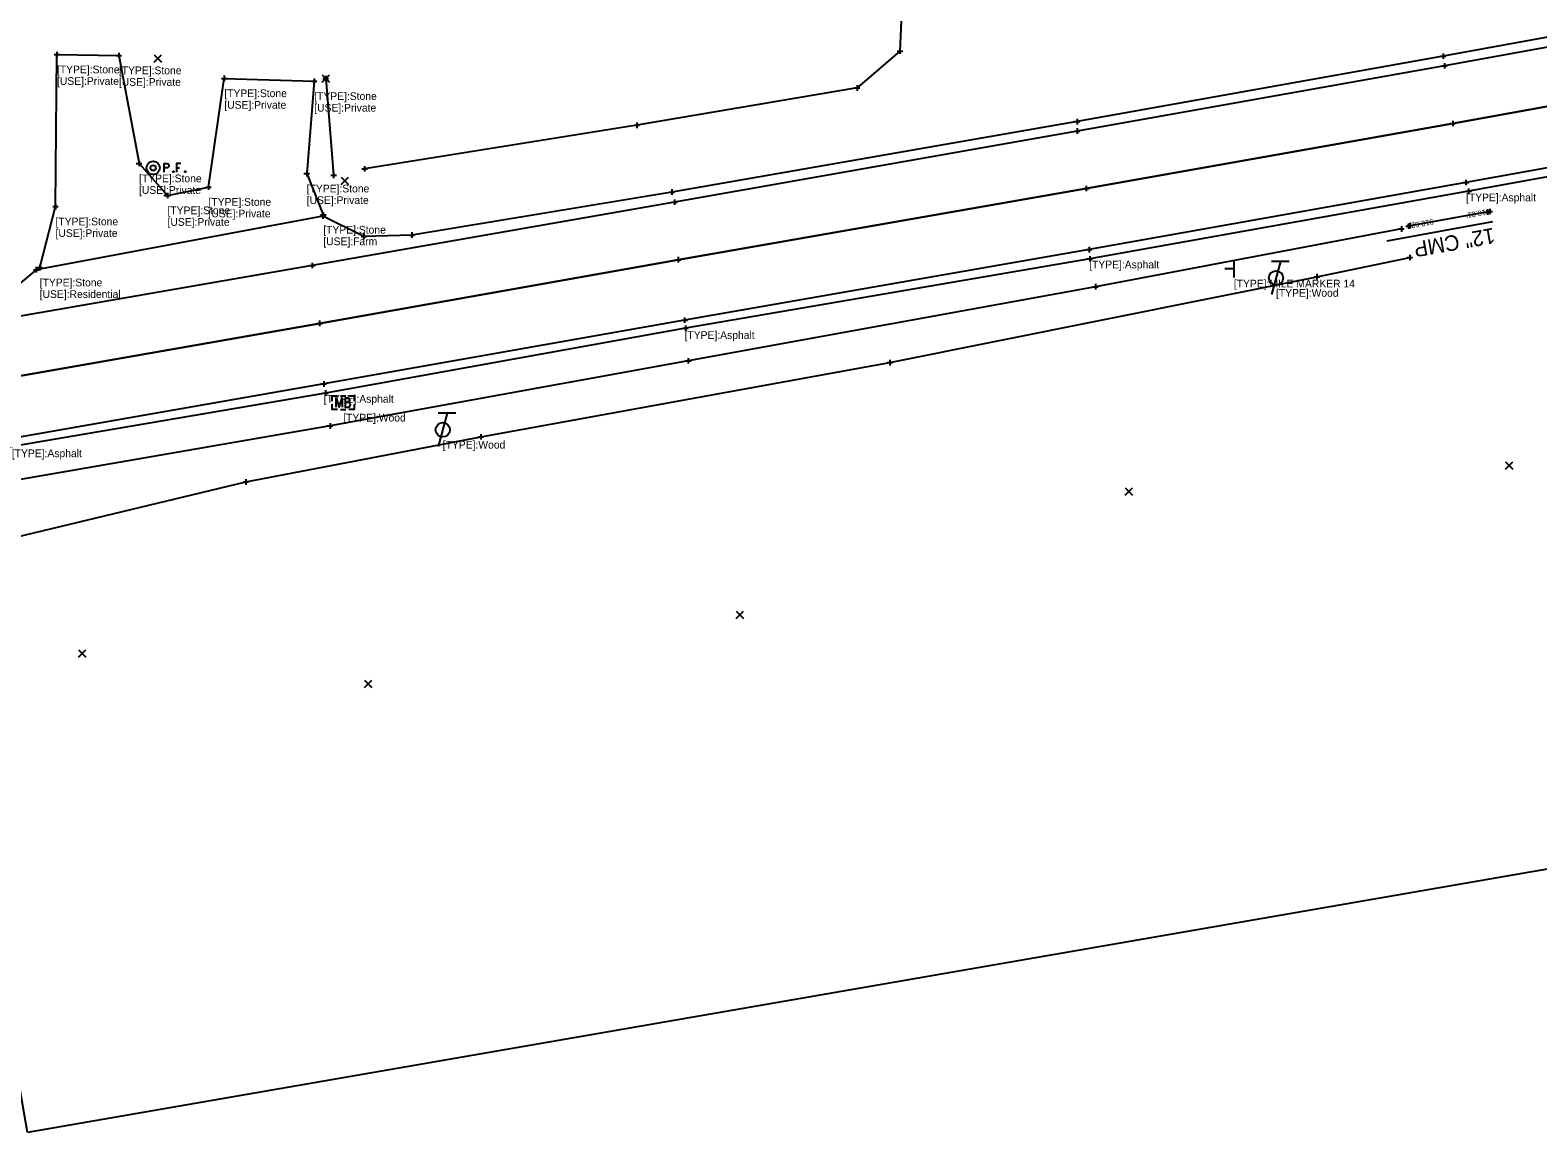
# Model space of a CAD drawing. Extents: x 1386013 to 1389776, y 604170 to 607009.
# Drawn here: x 1388733.1 to 1389006.3, y 604902.7 to 605103.7 of the extents above; entities that cross this region are included whole.
import ezdxf

# ---------------------------------------------------------------- set-up
doc = ezdxf.new("R2010")
doc.units = 0
for name, color, linetype in [('DR_X_Elev_Flow', 7, 'Continuous'), ('DR_X_Storm_Sewer', 7, 'Continuous'), ('DR_X_Text', 7, 'Continuous'), ('DV_X_Text', 7, 'Continuous'), ('PM_X_CL_Double_Solid', 7, 'Continuous'), ('PV_X_COP', 7, 'Continuous'), ('PV_X_Driveway', 7, 'Continuous'), ('PV_X_EOP', 7, 'Continuous'), ('PV_X_Shoulder', 7, 'Continuous'), ('RD_X_Cells', 7, 'Continuous'), ('RD_X_Fence', 7, 'Continuous'), ('SC_Scratch1', 7, 'Continuous'), ('SH_Cut_Line', 7, 'Continuous'), ('SN_X_Public', 7, 'Continuous'), ('SV_X_Random_Point', 7, 'Continuous'), ('SV_X_Text', 7, 'Continuous'), ('SV_X_Toe_of_Slope', 7, 'Continuous'), ('SV_X_Top_of_Bank', 7, 'Continuous'), ('UT_X_Telecom_Cells', 7, 'Continuous')]:
    doc.layers.add(name, color=color, linetype=linetype)

msp = doc.modelspace()

# ---------------------------------------------------------------- linework, layer by layer
at = {"layer": 'DR_X_Elev_Flow'}
for p, q in [((1388997.1, 605070.86), (1388998.1, 605070.86)), ((1388997.6, 605071.36), (1388997.6, 605070.36)), ((1388997.6, 605070.86), (1388997.6, 605070.86)), ((1388982.36, 605068.2), (1388983.36, 605068.2)), ((1388982.86, 605068.7), (1388982.86, 605067.7)), ((1388982.86, 605068.2), (1388982.86, 605068.2))]:
    msp.add_line(p, q, dxfattribs=at)
at = {"layer": 'DR_X_Storm_Sewer'}
msp.add_line((1388997.6, 605070.86), (1388982.86, 605068.2), dxfattribs=at)
at = {"layer": 'DR_X_Text'}
msp.add_line((1388979.02, 605065.57), (1388998.18, 605069.03), dxfattribs=at)
at = {"layer": 'DV_X_Text'}
for p, q in [((1388737.98, 605099.78), (1388737.98, 605098.78)), ((1388749.2, 605099.62), (1388749.2, 605098.62)), ((1388890.22, 605099.89), (1388891.22, 605099.89)), ((1388890.72, 605100.39), (1388890.72, 605099.39)), ((1388890.72, 605099.89), (1388890.72, 605099.89)), ((1388989.16, 605099.49), (1388989.16, 605098.49)), ((1388737.48, 605099.28), (1388738.48, 605099.28)), ((1388737.98, 605099.28), (1388737.98, 605099.28)), ((1388748.7, 605099.12), (1388749.7, 605099.12)), ((1388749.2, 605099.12), (1388749.2, 605099.12)), ((1388988.66, 605098.99), (1388989.66, 605098.99)), ((1388988.89, 605097.25), (1388989.89, 605097.25)), ((1388989.16, 605098.99), (1388989.16, 605098.99)), ((1388989.39, 605097.75), (1388989.39, 605096.75)), ((1388989.39, 605097.25), (1388989.39, 605097.25)), ((1388767.8, 605094.97), (1388768.8, 605094.97)), ((1388768.3, 605095.47), (1388768.3, 605094.47)), ((1388768.3, 605094.97), (1388768.3, 605094.97)), ((1388784.09, 605094.45), (1388785.09, 605094.45)), ((1388784.59, 605094.95), (1388784.59, 605093.95)), ((1388784.59, 605094.45), (1388784.59, 605094.45)), ((1388786.18, 605094.92), (1388787.18, 605094.92)), ((1388786.68, 605095.42), (1388786.68, 605094.42)), ((1388786.68, 605094.92), (1388786.68, 605094.92)), ((1388882.48, 605093.24), (1388883.48, 605093.24)), ((1388882.98, 605093.74), (1388882.98, 605092.74)), ((1388882.98, 605093.24), (1388882.98, 605093.24)), ((1388842.55, 605086.47), (1388843.55, 605086.47)), ((1388843.05, 605086.97), (1388843.05, 605085.97)), ((1388843.05, 605086.47), (1388843.05, 605086.47)), ((1388922.31, 605087.13), (1388923.31, 605087.13)), ((1388922.81, 605087.63), (1388922.81, 605086.63)), ((1388922.81, 605087.13), (1388922.81, 605087.13)), ((1388922.83, 605085.93), (1388922.83, 605084.93)), ((1388990.4, 605086.8), (1388991.4, 605086.8)), ((1388990.9, 605087.3), (1388990.9, 605086.3)), ((1388990.9, 605086.8), (1388990.9, 605086.8)), ((1388922.33, 605085.43), (1388923.33, 605085.43)), ((1388922.83, 605085.43), (1388922.83, 605085.43)), ((1388752.35, 605079.55), (1388753.35, 605079.55)), ((1388752.85, 605080.05), (1388752.85, 605079.05)), ((1388752.85, 605079.55), (1388752.85, 605079.55)), ((1388782.73, 605077.71), (1388783.73, 605077.71)), ((1388783.23, 605078.21), (1388783.23, 605077.21)), ((1388783.23, 605077.71), (1388783.23, 605077.71)), ((1388788.1, 605077.91), (1388788.1, 605076.91)), ((1388793.22, 605078.57), (1388794.22, 605078.57)), ((1388793.72, 605079.07), (1388793.72, 605078.07)), ((1388793.72, 605078.57), (1388793.72, 605078.57)), ((1388764.94, 605075.29), (1388765.94, 605075.29)), ((1388765.44, 605075.79), (1388765.44, 605074.79)), ((1388765.44, 605075.29), (1388765.44, 605075.29)), ((1388787.6, 605077.41), (1388788.6, 605077.41)), ((1388788.1, 605077.41), (1388788.1, 605077.41)), ((1388849.4, 605074.88), (1388849.4, 605073.88)), ((1388923.99, 605075.02), (1388924.99, 605075.02)), ((1388924.49, 605075.52), (1388924.49, 605074.52)), ((1388924.49, 605075.02), (1388924.49, 605075.02)), ((1388992.79, 605076.1), (1388993.79, 605076.1)), ((1388993.29, 605076.6), (1388993.29, 605075.6)), ((1388993.29, 605076.1), (1388993.29, 605076.1)), ((1388993.76, 605075.01), (1388993.76, 605074.01)), ((1388737.72, 605072.24), (1388737.72, 605071.24)), ((1388757.51, 605073.76), (1388758.51, 605073.76)), ((1388758.01, 605074.26), (1388758.01, 605073.26)), ((1388758.01, 605073.76), (1388758.01, 605073.76)), ((1388848.9, 605074.38), (1388849.9, 605074.38)), ((1388849.36, 605072.55), (1388850.36, 605072.55)), ((1388849.4, 605074.38), (1388849.4, 605074.38)), ((1388849.86, 605073.05), (1388849.86, 605072.05)), ((1388849.86, 605072.55), (1388849.86, 605072.55)), ((1388993.26, 605074.51), (1388994.26, 605074.51)), ((1388993.76, 605074.51), (1388993.76, 605074.51)), ((1388737.22, 605071.74), (1388738.22, 605071.74)), ((1388737.72, 605071.74), (1388737.72, 605071.74)), ((1388785.66, 605070.01), (1388786.66, 605070.01)), ((1388785.73, 605070.25), (1388786.73, 605070.25)), ((1388786.16, 605070.51), (1388786.16, 605069.51)), ((1388786.16, 605070.01), (1388786.16, 605070.01)), ((1388786.23, 605070.75), (1388786.23, 605069.75)), ((1388786.23, 605070.25), (1388786.23, 605070.25)), ((1388996.7, 605070.73), (1388997.7, 605070.73)), ((1388997.2, 605071.23), (1388997.2, 605070.23)), ((1388997.2, 605070.73), (1388997.2, 605070.73)), ((1388793.59, 605066.84), (1388793.59, 605065.84)), ((1388801.79, 605066.59), (1388802.79, 605066.59)), ((1388802.29, 605067.09), (1388802.29, 605066.09)), ((1388802.29, 605066.59), (1388802.29, 605066.59)), ((1388981.1, 605067.69), (1388982.1, 605067.69)), ((1388981.6, 605068.19), (1388981.6, 605067.19)), ((1388981.6, 605067.69), (1388981.6, 605067.69)), ((1388982.6, 605068.3), (1388983.6, 605068.3)), ((1388983.1, 605068.8), (1388983.1, 605067.8)), ((1388983.1, 605068.3), (1388983.1, 605068.3)), ((1388793.09, 605066.34), (1388794.09, 605066.34)), ((1388793.59, 605066.34), (1388793.59, 605066.34)), ((1388924.51, 605063.95), (1388925.51, 605063.95)), ((1388925.01, 605064.45), (1388925.01, 605063.45)), ((1388925.01, 605063.95), (1388925.01, 605063.95)), ((1388734.85, 605061.19), (1388734.85, 605060.19)), ((1388783.75, 605061.08), (1388784.75, 605061.08)), ((1388784.25, 605061.58), (1388784.25, 605060.58)), ((1388784.25, 605061.08), (1388784.25, 605061.08)), ((1388850.05, 605062.12), (1388851.05, 605062.12)), ((1388850.55, 605062.62), (1388850.55, 605061.62)), ((1388850.55, 605062.12), (1388850.55, 605062.12)), ((1388924.64, 605062.29), (1388925.64, 605062.29)), ((1388925.14, 605062.79), (1388925.14, 605061.79)), ((1388925.14, 605062.29), (1388925.14, 605062.29)), ((1388982.61, 605062.53), (1388983.61, 605062.53)), ((1388983.11, 605063.03), (1388983.11, 605062.03)), ((1388983.11, 605062.53), (1388983.11, 605062.53)), ((1388733.73, 605060.31), (1388734.73, 605060.31)), ((1388734.23, 605060.81), (1388734.23, 605059.81)), ((1388734.23, 605060.31), (1388734.23, 605060.31)), ((1388734.35, 605060.69), (1388735.35, 605060.69)), ((1388734.85, 605060.69), (1388734.85, 605060.69)), ((1388965.76, 605059.04), (1388966.76, 605059.04)), ((1388966.26, 605059.54), (1388966.26, 605058.54)), ((1388966.26, 605059.04), (1388966.26, 605059.04)), ((1388925.66, 605057.23), (1388926.66, 605057.23)), ((1388926.16, 605057.73), (1388926.16, 605056.73)), ((1388926.16, 605057.23), (1388926.16, 605057.23)), ((1388785.05, 605050.58), (1388786.05, 605050.58)), ((1388785.55, 605051.08), (1388785.55, 605050.08)), ((1388785.55, 605050.58), (1388785.55, 605050.58)), ((1388851.2, 605051.17), (1388852.2, 605051.17)), ((1388851.7, 605051.67), (1388851.7, 605050.67)), ((1388851.7, 605051.17), (1388851.7, 605051.17)), ((1388851.88, 605050.21), (1388851.88, 605049.21)), ((1388851.38, 605049.71), (1388852.38, 605049.71)), ((1388851.88, 605049.71), (1388851.88, 605049.71)), ((1388851.88, 605043.81), (1388852.88, 605043.81)), ((1388852.38, 605044.31), (1388852.38, 605043.31)), ((1388852.38, 605043.81), (1388852.38, 605043.81)), ((1388888.42, 605043.48), (1388889.42, 605043.48)), ((1388888.92, 605043.98), (1388888.92, 605042.98)), ((1388888.92, 605043.48), (1388888.92, 605043.48)), ((1388785.81, 605039.62), (1388786.81, 605039.62)), ((1388786.31, 605040.12), (1388786.31, 605039.12)), ((1388786.31, 605039.62), (1388786.31, 605039.62)), ((1388786.12, 605037.96), (1388787.12, 605037.96)), ((1388786.62, 605038.46), (1388786.62, 605037.46)), ((1388786.62, 605037.96), (1388786.62, 605037.96)), ((1388786.96, 605032), (1388787.96, 605032)), ((1388787.46, 605032.5), (1388787.46, 605031.5)), ((1388787.46, 605032), (1388787.46, 605032)), ((1388814.27, 605030.03), (1388815.27, 605030.03)), ((1388814.77, 605030.53), (1388814.77, 605029.53)), ((1388814.77, 605030.03), (1388814.77, 605030.03)), ((1388771.71, 605021.87), (1388772.71, 605021.87)), ((1388772.21, 605022.37), (1388772.21, 605021.37)), ((1388772.21, 605021.87), (1388772.21, 605021.87))]:
    msp.add_line(p, q, dxfattribs=at)
at = {"layer": 'PM_X_CL_Double_Solid'}
msp.add_lwpolyline([(1387998.85, 604914.97), (1388072.27, 604927.44), (1388150.34, 604940.54), (1388219.83, 604952.56), (1388327.21, 604971.05), (1388378.93, 604979.71), (1388451.75, 604991.99), (1388527.19, 605005.2), (1388605.28, 605019.17), (1388650.04, 605026.96), (1388727.22, 605040.35), (1388785.55, 605050.58), (1388850.55, 605062.12), (1388924.49, 605075.02), (1388990.9, 605086.8), (1389068.68, 605100.88), (1389141.9, 605114.3), (1389207.53, 605126.39), (1389280.37, 605139.49)], dxfattribs=at)
at = {"layer": 'PV_X_COP'}
msp.add_lwpolyline([(1389280.37, 605139.49), (1389207.53, 605126.39), (1389141.9, 605114.3), (1389068.68, 605100.88), (1388990.9, 605086.8), (1388924.49, 605075.02), (1388850.55, 605062.12), (1388785.55, 605050.58), (1388727.22, 605040.35), (1388650.04, 605026.96), (1388605.28, 605019.17), (1388527.19, 605005.2), (1388451.75, 604991.99), (1388378.93, 604979.71), (1388327.21, 604971.05), (1388219.83, 604952.56), (1388150.34, 604940.54), (1388072.27, 604927.44), (1387998.85, 604914.97)], dxfattribs=at)
at = {"layer": 'PV_X_Driveway'}
msp.add_lwpolyline([(1388734.85, 605060.69), (1388737.72, 605071.74), (1388737.98, 605099.28), (1388749.2, 605099.12), (1388752.85, 605079.55), (1388758.01, 605073.76), (1388765.44, 605075.29), (1388768.3, 605094.97), (1388784.59, 605094.45), (1388783.23, 605077.71), (1388786.23, 605070.25)], dxfattribs=at)
at = {"layer": 'PV_X_EOP'}
for points in [[(1389278.61, 605149.89), (1389205.62, 605136.54), (1389139.99, 605124.61), (1389067.04, 605111.39), (1388989.39, 605097.25), (1388922.83, 605085.43), (1388849.86, 605072.55), (1388784.25, 605061.08), (1388726.08, 605051), (1388647.73, 605037.35), (1388603.87, 605029.52), (1388525.26, 605015.57), (1388450.62, 605002.62), (1388377.29, 604990.08), (1388325.54, 604981.41), (1388218.94, 604963.01), (1388149.68, 604951.27), (1388070.9, 604937.92), (1387997.67, 604925.46)], [(1389281.27, 605129.06), (1389208.5, 605115.45), (1389143.42, 605103.48), (1389070.14, 605089.92), (1388993.29, 605076.1), (1388925.01, 605063.95), (1388851.7, 605051.17), (1388786.31, 605039.62), (1388729.8, 605029.75), (1388651.59, 605016.29), (1388606.27, 605008.43), (1388528.77, 604994.59), (1388453.6, 604981.36), (1388380.25, 604968.93), (1388328.49, 604960.28), (1388221.37, 604941.87), (1388151.14, 604929.78), (1388073.48, 604916.74), (1388000.2, 604904.18)]]:
    msp.add_lwpolyline(points, dxfattribs=at)
at = {"layer": 'PV_X_Shoulder'}
for points in [[(1389278.32, 605151.38), (1389205.26, 605138.27), (1389139.52, 605126.2), (1389066.77, 605113.2), (1388989.16, 605098.99), (1388922.81, 605087.13), (1388849.4, 605074.38), (1388802.29, 605066.59), (1388793.59, 605066.34), (1388786.16, 605070.01), (1388734.23, 605060.31), (1388725.78, 605053.3), (1388647.71, 605038.75), (1388603.54, 605031.12), (1388524.83, 605017.38), (1388449.88, 605004.12), (1388377.38, 604991.89), (1388326.15, 604983.28), (1388218.46, 604964.95), (1388149.62, 604953.16), (1388070.88, 604939.75), (1387997.08, 604927.24)], [(1389070.3, 605088.44), (1388993.76, 605074.51), (1388925.14, 605062.29), (1388851.88, 605049.71), (1388786.62, 605037.96), (1388729.92, 605028.26), (1388651.51, 605014.41), (1388606.72, 605006.79), (1388529.08, 604992.77), (1388453.76, 604979.45), (1388380.57, 604967.56), (1388328.47, 604958.58), (1388293.07, 604951.05), (1388291.51, 604952.1), (1388221.65, 604940.36), (1388151.37, 604928.17), (1388118.45, 604921.92), (1388113.87, 604918.91), (1388113.3, 604917.2), (1388092.34, 604913.82), (1388086.61, 604916.75), (1388073.66, 604915.38), (1388000.63, 604902.69)]]:
    msp.add_lwpolyline(points, dxfattribs=at)
at = {"layer": 'RD_X_Cells'}
for p, q in [((1388789.33, 605037.44), (1388790.33, 605037.44)), ((1388789.33, 605034.99), (1388790.33, 605034.99)), ((1388789.84, 605036.21), (1388789.84, 605036.21))]:
    msp.add_line(p, q, dxfattribs=at)
for points in [[(1388787.84, 605036.47), (1388787.84, 605037.44), (1388788.81, 605037.44)], [(1388788.54, 605035.41), (1388788.54, 605037.01), (1388789.12, 605035.41), (1388789.68, 605037.01), (1388789.68, 605035.41)], [(1388790.86, 605036.28), (1388790.92, 605036.35), (1388790.96, 605036.38), (1388790.99, 605036.42), (1388791, 605036.45), (1388791.02, 605036.5), (1388791.04, 605036.54), (1388791.06, 605036.62), (1388791.06, 605036.66), (1388791.06, 605036.71), (1388791.05, 605036.79), (1388791.02, 605036.85), (1388790.99, 605036.9), (1388790.92, 605036.95), (1388790.87, 605036.98), (1388790.85, 605036.99), (1388790.79, 605037.01), (1388790.17, 605037.01), (1388790.17, 605035.41), (1388790.86, 605035.41), (1388790.95, 605035.46), (1388791.02, 605035.53), (1388791.09, 605035.63), (1388791.13, 605035.74), (1388791.14, 605035.86), (1388791.14, 605035.93), (1388791.11, 605036.01), (1388791.06, 605036.12), (1388791, 605036.2), (1388790.86, 605036.28), (1388790.17, 605036.28)], [(1388790.85, 605037.44), (1388791.84, 605037.44), (1388791.84, 605036.47)], [(1388788.81, 605034.99), (1388787.84, 605034.99), (1388787.84, 605035.96)], [(1388791.84, 605035.96), (1388791.84, 605034.99), (1388790.85, 605034.99)]]:
    msp.add_lwpolyline(points, dxfattribs=at)
at = {"layer": 'RD_X_Fence'}
for points in [[(1388892.34, 605137.04), (1388890.72, 605099.89), (1388882.98, 605093.24), (1388843.05, 605086.47), (1388793.72, 605078.57)], [(1388786.68, 605094.92), (1388788.1, 605077.41)]]:
    msp.add_lwpolyline(points, dxfattribs=at)
at = {"layer": 'SC_Scratch1'}
for points in [[(1388757.4, 605077.95), (1388757.4, 605079.55), (1388757.93, 605079.55), (1388757.98, 605079.53), (1388758.06, 605079.51), (1388758.09, 605079.48), (1388758.13, 605079.46), (1388758.17, 605079.4), (1388758.2, 605079.33), (1388758.23, 605079.23), (1388758.23, 605079.08), (1388758.22, 605079.03), (1388758.19, 605078.95), (1388758.15, 605078.87), (1388758.11, 605078.83), (1388758.07, 605078.8), (1388758.02, 605078.78), (1388757.93, 605078.77), (1388757.4, 605078.77)], [(1388759.04, 605078.16), (1388759.1, 605078.16), (1388759.13, 605078.14), (1388759.16, 605078.09), (1388759.16, 605078.02), (1388759.13, 605077.97), (1388759.1, 605077.95), (1388759.04, 605077.95), (1388759.01, 605077.97), (1388758.98, 605078.02), (1388758.98, 605078.09), (1388759.01, 605078.14), (1388759.04, 605078.16)], [(1388760.41, 605079.55), (1388759.65, 605079.55), (1388759.65, 605077.95)], [(1388759.65, 605078.77), (1388760.19, 605078.77)], [(1388761.19, 605078.16), (1388761.25, 605078.16), (1388761.28, 605078.14), (1388761.31, 605078.09), (1388761.31, 605078.02), (1388761.28, 605077.97), (1388761.25, 605077.95), (1388761.19, 605077.95), (1388761.16, 605077.97), (1388761.13, 605078.02), (1388761.13, 605078.09), (1388761.16, 605078.14), (1388761.19, 605078.16)]]:
    msp.add_lwpolyline(points, dxfattribs=at)
for radius in [1.2, 0.495]:
    msp.add_circle((1388755.4, 605078.75), radius, dxfattribs=at)
at = {"layer": 'SH_Cut_Line'}
msp.add_lwpolyline([(1388732.63, 604904.03), (1388695.08, 605120.8), (1389030.09, 605178.83), (1389067.64, 604962.06)], close=True, dxfattribs=at)
at = {"layer": 'SN_X_Public'}
for p, q in [((1388951.22, 605062.09), (1388951.22, 605058.89)), ((1388951.22, 605060.49), (1388949.62, 605060.49))]:
    msp.add_line(p, q, dxfattribs=at)
at = {"layer": 'SV_X_Random_Point'}
for p, q in [((1388755.61, 605097.93), (1388756.94, 605099.26)), ((1388755.61, 605099.26), (1388756.94, 605097.93)), ((1388786.05, 605094.3), (1388787.38, 605095.63)), ((1388786.05, 605095.63), (1388787.38, 605094.3)), ((1388789.46, 605075.75), (1388790.8, 605077.09)), ((1388789.46, 605077.09), (1388790.8, 605075.75)), ((1389000.46, 605024.15), (1389001.8, 605025.49)), ((1389000.46, 605025.49), (1389001.8, 605024.15)), ((1388931.55, 605019.44), (1388932.88, 605020.77)), ((1388931.55, 605020.77), (1388932.88, 605019.44)), ((1388861.07, 604997.13), (1388862.4, 604998.46)), ((1388861.07, 604998.46), (1388862.4, 604997.13)), ((1388741.88, 604990.12), (1388743.21, 604991.46)), ((1388741.88, 604991.46), (1388743.21, 604990.12)), ((1388793.72, 604984.64), (1388795.05, 604985.97)), ((1388793.72, 604985.97), (1388795.05, 604984.64))]:
    msp.add_line(p, q, dxfattribs=at)
at = {"layer": 'SV_X_Toe_of_Slope'}
msp.add_lwpolyline([(1388981.6, 605067.69), (1388926.16, 605057.23), (1388852.38, 605043.81), (1388787.46, 605032), (1388730.99, 605022.22), (1388651.29, 605009.18), (1388603.25, 604999.21), (1388564.46, 604991.1)], dxfattribs=at)
at = {"layer": 'SV_X_Top_of_Bank'}
msp.add_lwpolyline([(1388562.07, 604985.53), (1388598.86, 604991.18), (1388647.29, 604997.3), (1388724.16, 605010.34), (1388772.21, 605021.87), (1388814.77, 605030.03), (1388888.92, 605043.48), (1388966.26, 605059.04), (1388983.11, 605062.53)], dxfattribs=at)
at = {"layer": 'UT_X_Telecom_Cells'}
for p, q in [((1388961.26, 605061.81), (1388958.06, 605061.81)), ((1388959.66, 605061.81), (1388958.06, 605055.81)), ((1388810.28, 605034.31), (1388807.08, 605034.31)), ((1388808.68, 605034.31), (1388807.08, 605028.31))]:
    msp.add_line(p, q, dxfattribs=at)
for centre in [(1388958.86, 605058.81), (1388807.88, 605031.31)]:
    msp.add_circle(centre, 1.3, dxfattribs=at)

# ---------------------------------------------------------------- texts
at = {"layer": 'DR_X_Text'}
msp.add_text('12" CMP', height=2.8, rotation=190.2381, dxfattribs=at).set_placement((1388998.26, 605067.93))
at = {"layer": 'SC_Scratch1'}
for s, p in [("910.62'", (1388987.3, 605069.51)), ("910.81'", (1388997.51, 605071.35))]:
    msp.add_text(s, height=1, rotation=190.2381, dxfattribs=at).set_placement(p)
at = {"layer": 'SV_X_Text'}
for s, p in [('[TYPE]:Stone', (1388737.98, 605095.88)), ('[TYPE]:Stone', (1388749.2, 605095.72)), ('[USE]:Private', (1388737.98, 605093.78)), ('[USE]:Private', (1388749.2, 605093.62)), ('[TYPE]:Stone', (1388768.3, 605091.57)), ('[TYPE]:Stone', (1388784.59, 605091.05)), ('[USE]:Private', (1388768.3, 605089.47)), ('[USE]:Private', (1388784.59, 605088.95)), ('[TYPE]:Stone', (1388752.85, 605076.15)), ('[USE]:Private', (1388752.85, 605074.05)), ('[TYPE]:Stone', (1388783.23, 605074.31)), ('[TYPE]:Stone', (1388765.44, 605071.89)), ('[USE]:Private', (1388783.23, 605072.21)), ('[TYPE]:Asphalt', (1388993.29, 605072.7)), ('[TYPE]:Stone', (1388737.72, 605068.34)), ('[TYPE]:Stone', (1388758.01, 605070.36)), ('[USE]:Private', (1388758.01, 605068.26)), ('[USE]:Private', (1388765.44, 605069.79)), ('[USE]:Private', (1388737.72, 605066.24)), ('[TYPE]:Stone', (1388786.23, 605066.85)), ('[USE]:Farm', (1388786.23, 605064.75)), ('[TYPE]:Asphalt', (1388925.01, 605060.55)), ('[TYPE]:Stone', (1388734.85, 605057.29)), ('[TYPE]:MILE MARKER 14', (1388951.22, 605057.09)), ('[USE]:Residential', (1388734.85, 605055.19)), ('[TYPE]:Wood', (1388958.86, 605055.41)), ('[TYPE]:Asphalt', (1388851.7, 605047.77)), ('[TYPE]:Asphalt', (1388786.31, 605036.22)), ('[TYPE]:Wood', (1388789.84, 605032.81)), ('[TYPE]:Wood', (1388807.88, 605027.91)), ('[TYPE]:Asphalt', (1388729.8, 605026.35))]:
    msp.add_text(s, height=1.4, dxfattribs=at).set_placement(p)

doc.saveas('drawing.dxf')
